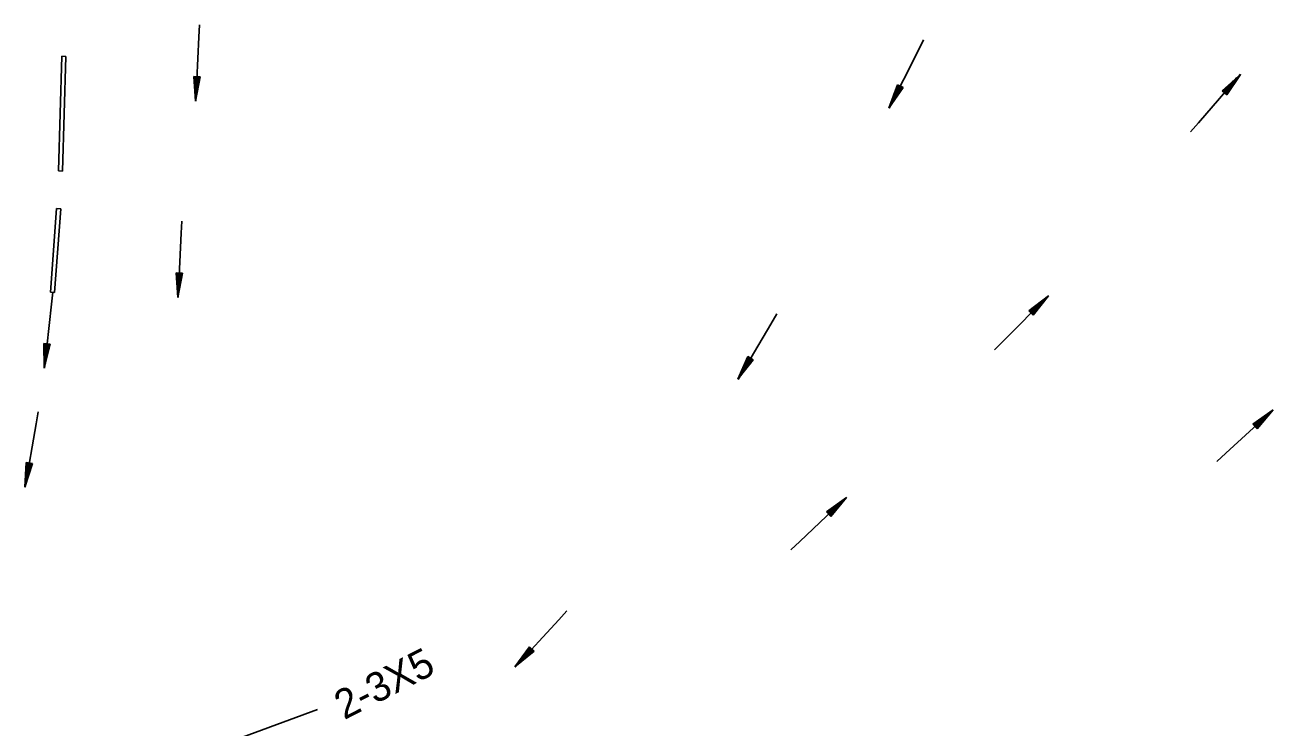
# Model space of a CAD drawing. Extents: x 1308292 to 1312792, y 238563 to 242743.
# Drawn here: x 1309923 to 1310520, y 240614 to 240949 of the extents above; entities that cross this region are included whole.
import ezdxf

# ---------------------------------------------------------------- set-up
doc = ezdxf.new("R2010")
doc.units = 0
for name, color, linetype in [('R_BRIDGE OLD', 7, 'Continuous'), ('R_Flow Arrows', 7, 'Continuous'), ('R_Pipe Culvert', 7, 'Continuous')]:
    doc.layers.add(name, color=color, linetype=linetype)

msp = doc.modelspace()

# ---------------------------------------------------------------- linework, layer by layer
at = {"layer": 'R_BRIDGE OLD'}
msp.add_line((1309945.82, 240579.12), (1310063.23, 240622.23), dxfattribs=at)
at = {"layer": 'R_Flow Arrows'}
for p, q in [((1310004.01, 240924.75), (1310004.83, 240912.93)), ((1310007.04, 240924.57), (1310004.01, 240924.75)), ((1310007.04, 240924.57), (1310004.83, 240912.93)), ((1310495.6, 240917.97), (1310504.52, 240925.76)), ((1310497.88, 240915.95), (1310504.52, 240925.76)), ((1310340.41, 240920.82), (1310336.36, 240909.68)), ((1310343.11, 240919.42), (1310336.36, 240909.68)), ((1310343.11, 240919.42), (1310340.41, 240920.82)), ((1310495.6, 240917.97), (1310497.88, 240915.95)), ((1309995.55, 240830.99), (1309996.37, 240819.18)), ((1309998.58, 240830.81), (1309995.55, 240830.99)), ((1309998.58, 240830.81), (1309996.37, 240819.18)), ((1310403.27, 240812.78), (1310412.7, 240819.94)), ((1310405.4, 240810.61), (1310412.7, 240819.94)), ((1310403.27, 240812.78), (1310405.4, 240810.61)), ((1309932.42, 240797.21), (1309932.55, 240785.36)), ((1309935.44, 240796.85), (1309932.42, 240797.21)), ((1309935.44, 240796.85), (1309932.55, 240785.36)), ((1310268.91, 240790.9), (1310264.11, 240780.07)), ((1310271.51, 240789.32), (1310264.11, 240780.07)), ((1310271.51, 240789.32), (1310268.91, 240790.9)), ((1310510.31, 240758.61), (1310520, 240765.43)), ((1310512.37, 240756.37), (1310520, 240765.43)), ((1310510.31, 240758.61), (1310512.37, 240756.37)), ((1309923.95, 240740.33), (1309923.33, 240728.5)), ((1309926.94, 240739.78), (1309923.33, 240728.5)), ((1309926.94, 240739.78), (1309923.95, 240740.33)), ((1310306.51, 240716.71), (1310316.16, 240723.57)), ((1310308.57, 240714.47), (1310316.16, 240723.57)), ((1310306.51, 240716.71), (1310308.57, 240714.47)), ((1310164.54, 240652.2), (1310157.6, 240642.59)), ((1310166.76, 240650.11), (1310157.6, 240642.59)), ((1310166.76, 240650.11), (1310164.54, 240652.2))]:
    msp.add_line(p, q, dxfattribs=at)
for points in [[(1310006.75, 240949.37), (1310006.49, 240943.61), (1310004.98, 240912.92)], [(1310352.91, 240942.2), (1310350.33, 240937.05), (1310336.49, 240909.61)], [(1310004.31, 240924.73), (1310004.17, 240922.38)], [(1310004.61, 240924.71), (1310004.34, 240920.02)], [(1310004.92, 240924.69), (1310004.55, 240918.49), (1310004.5, 240917.66)], [(1310005.22, 240924.68), (1310004.85, 240918.47), (1310004.65, 240915.29)], [(1310005.83, 240924.64), (1310005.46, 240918.43), (1310005.26, 240915.26)], [(1310006.13, 240924.62), (1310005.76, 240918.41), (1310005.71, 240917.58)], [(1310006.44, 240924.6), (1310006.16, 240919.91)], [(1310006.74, 240924.58), (1310006.6, 240922.24)], [(1310480.54, 240898.26), (1310484.3, 240902.63), (1310504.41, 240925.86)], [(1310496.51, 240917.16), (1310500.63, 240921.82), (1310502.75, 240924.2)], [(1310496.97, 240916.76), (1310501.09, 240921.41), (1310503.2, 240923.79)], [(1310341.49, 240920.26), (1310338.63, 240914.73), (1310337.16, 240911.91)], [(1310342.03, 240919.98), (1310339.17, 240914.45), (1310337.7, 240911.63)], [(1310341.22, 240920.4), (1310338.36, 240914.87), (1310337.98, 240914.14)], [(1310340.95, 240920.54), (1310338.79, 240916.36)], [(1310342.3, 240919.84), (1310339.44, 240914.31), (1310339.05, 240913.58)], [(1310340.68, 240920.68), (1310339.6, 240918.59)], [(1310342.57, 240919.7), (1310340.41, 240915.52)], [(1310342.84, 240919.56), (1310341.76, 240917.47)], [(1310495.83, 240917.76), (1310497.39, 240919.52)], [(1310496.06, 240917.56), (1310499.17, 240921.08)], [(1310496.28, 240917.36), (1310500.4, 240922.02), (1310500.96, 240922.64)], [(1310497.2, 240916.56), (1310501.31, 240921.21), (1310501.87, 240921.83)], [(1310497.42, 240916.35), (1310500.54, 240919.88)], [(1310497.65, 240916.15), (1310499.21, 240917.91)], [(1309998.29, 240855.62), (1309998.03, 240849.86), (1309996.52, 240819.17)], [(1309995.85, 240830.98), (1309995.71, 240828.63)], [(1309996.15, 240830.96), (1309995.88, 240826.27)], [(1309996.46, 240830.94), (1309996.09, 240824.73), (1309996.04, 240823.9)], [(1309996.76, 240830.92), (1309996.39, 240824.72), (1309996.19, 240821.54)], [(1309997.37, 240830.89), (1309997, 240824.68), (1309996.8, 240821.5)], [(1309997.67, 240830.87), (1309997.3, 240824.66), (1309997.25, 240823.83)], [(1309997.98, 240830.85), (1309997.7, 240826.16)], [(1309998.28, 240830.83), (1309998.14, 240828.49)], [(1309936.62, 240821.62), (1309936.01, 240815.89), (1309932.7, 240785.34)], [(1310386.89, 240794.15), (1310390.94, 240798.25), (1310412.59, 240820.05)], [(1310403.91, 240812.13), (1310408.34, 240816.49), (1310408.93, 240817.08)], [(1310404.12, 240811.91), (1310408.55, 240816.28), (1310410.82, 240818.5)], [(1310404.55, 240811.48), (1310408.98, 240815.84), (1310411.25, 240818.07)], [(1310404.76, 240811.26), (1310409.19, 240815.63), (1310409.78, 240816.21)], [(1310282.85, 240811.38), (1310279.92, 240806.42), (1310264.24, 240780)], [(1310403.48, 240812.56), (1310405.16, 240814.21)], [(1310403.7, 240812.35), (1310407.04, 240815.65)], [(1310404.98, 240811.05), (1310408.32, 240814.35)], [(1310405.19, 240810.83), (1310406.86, 240812.48)], [(1309932.73, 240797.17), (1309932.45, 240794.84)], [(1309933.03, 240797.13), (1309932.47, 240792.47)], [(1309933.33, 240797.1), (1309932.6, 240790.93), (1309932.5, 240790.1)], [(1309933.63, 240797.06), (1309932.9, 240790.89), (1309932.51, 240787.73)], [(1309934.24, 240796.99), (1309933.5, 240790.82), (1309933.12, 240787.66)], [(1309934.54, 240796.96), (1309933.8, 240790.78), (1309933.7, 240789.95)], [(1309934.84, 240796.92), (1309934.28, 240792.25)], [(1309935.14, 240796.88), (1309934.86, 240794.55)], [(1310269.95, 240790.27), (1310266.72, 240784.96), (1310265.06, 240782.25)], [(1310270.47, 240789.96), (1310267.24, 240784.64), (1310265.58, 240781.93)], [(1310269.69, 240790.43), (1310266.46, 240785.12), (1310266.03, 240784.41)], [(1310269.43, 240790.59), (1310266.99, 240786.57)], [(1310270.73, 240789.8), (1310267.5, 240784.48), (1310267.06, 240783.77)], [(1310269.17, 240790.75), (1310267.95, 240788.74)], [(1310270.99, 240789.64), (1310268.55, 240785.62)], [(1310271.25, 240789.48), (1310270.03, 240787.47)], [(1309929.66, 240764.43), (1309928.7, 240758.75), (1309923.48, 240728.47)], [(1310493.13, 240740.74), (1310497.36, 240744.66), (1310520, 240765.43)], [(1310510.93, 240757.93), (1310515.51, 240762.14), (1310516.13, 240762.7)], [(1310511.14, 240757.71), (1310515.72, 240761.92), (1310518.07, 240764.06)], [(1310511.55, 240757.26), (1310516.13, 240761.47), (1310518.48, 240763.61)], [(1310510.52, 240758.38), (1310512.25, 240759.97)], [(1310510.73, 240758.16), (1310514.19, 240761.34)], [(1310511.75, 240757.04), (1310516.33, 240761.24), (1310516.95, 240761.8)], [(1310511.96, 240756.81), (1310515.42, 240759.99)], [(1310512.17, 240756.59), (1310513.9, 240758.18)], [(1309925.15, 240740.11), (1309924.03, 240733.99), (1309923.44, 240730.86)], [(1309924.85, 240740.16), (1309923.73, 240734.05), (1309923.58, 240733.23)], [(1309924.55, 240740.22), (1309923.7, 240735.59)], [(1309924.25, 240740.27), (1309923.83, 240737.96)], [(1309925.75, 240740), (1309924.63, 240733.88), (1309924.04, 240730.75)], [(1309926.05, 240739.94), (1309924.92, 240733.83), (1309924.77, 240733.01)], [(1309926.34, 240739.89), (1309925.5, 240735.26)], [(1309926.64, 240739.83), (1309926.22, 240737.52)], [(1310289.54, 240698.61), (1310293.72, 240702.58), (1310316.06, 240723.68)], [(1310307.12, 240716.04), (1310311.69, 240720.26), (1310312.3, 240720.82)], [(1310307.33, 240715.81), (1310311.9, 240720.04), (1310314.24, 240722.19)], [(1310307.74, 240715.37), (1310312.31, 240719.59), (1310314.65, 240721.74)], [(1310306.71, 240716.48), (1310308.44, 240718.08)], [(1310306.92, 240716.26), (1310310.37, 240719.45)], [(1310307.95, 240715.14), (1310312.51, 240719.37), (1310313.13, 240719.93)], [(1310308.16, 240714.92), (1310311.61, 240718.11)], [(1310308.36, 240714.7), (1310310.09, 240716.29)], [(1310182.41, 240669.36), (1310178.52, 240665.1), (1310157.72, 240642.49)], [(1310165.43, 240651.36), (1310161.17, 240646.83), (1310158.98, 240644.52)], [(1310165.87, 240650.95), (1310161.61, 240646.42), (1310159.43, 240644.1)], [(1310165.2, 240651.57), (1310160.95, 240647.04), (1310160.38, 240646.44)], [(1310166.09, 240650.74), (1310161.83, 240646.21), (1310161.26, 240645.6)], [(1310164.98, 240651.78), (1310161.76, 240648.35)], [(1310166.31, 240650.53), (1310163.09, 240647.11)], [(1310164.76, 240651.99), (1310163.15, 240650.28)], [(1310166.53, 240650.32), (1310164.92, 240648.61)]]:
    msp.add_lwpolyline(points, dxfattribs=at)
at = {"layer": 'R_Pipe Culvert'}
for p, q in [((1309939.29, 240879.65), (1309940.9, 240934.43)), ((1309942.9, 240934.37), (1309940.9, 240934.43)), ((1309942.9, 240934.37), (1309941.29, 240879.58)), ((1309941.29, 240879.58), (1309939.29, 240879.65)), ((1309935.47, 240821.72), (1309938.41, 240861.62)), ((1309940.4, 240861.5), (1309937.47, 240821.55)), ((1309940.4, 240861.5), (1309938.41, 240861.62)), ((1309937.47, 240821.55), (1309935.47, 240821.72))]:
    msp.add_line(p, q, dxfattribs=at)

# ---------------------------------------------------------------- texts
at = {"layer": 'R_BRIDGE OLD'}
msp.add_text('2-3X5', height=14, rotation=27.13195, dxfattribs=at).set_placement((1310075.94, 240617.11))

doc.saveas('drawing.dxf')
